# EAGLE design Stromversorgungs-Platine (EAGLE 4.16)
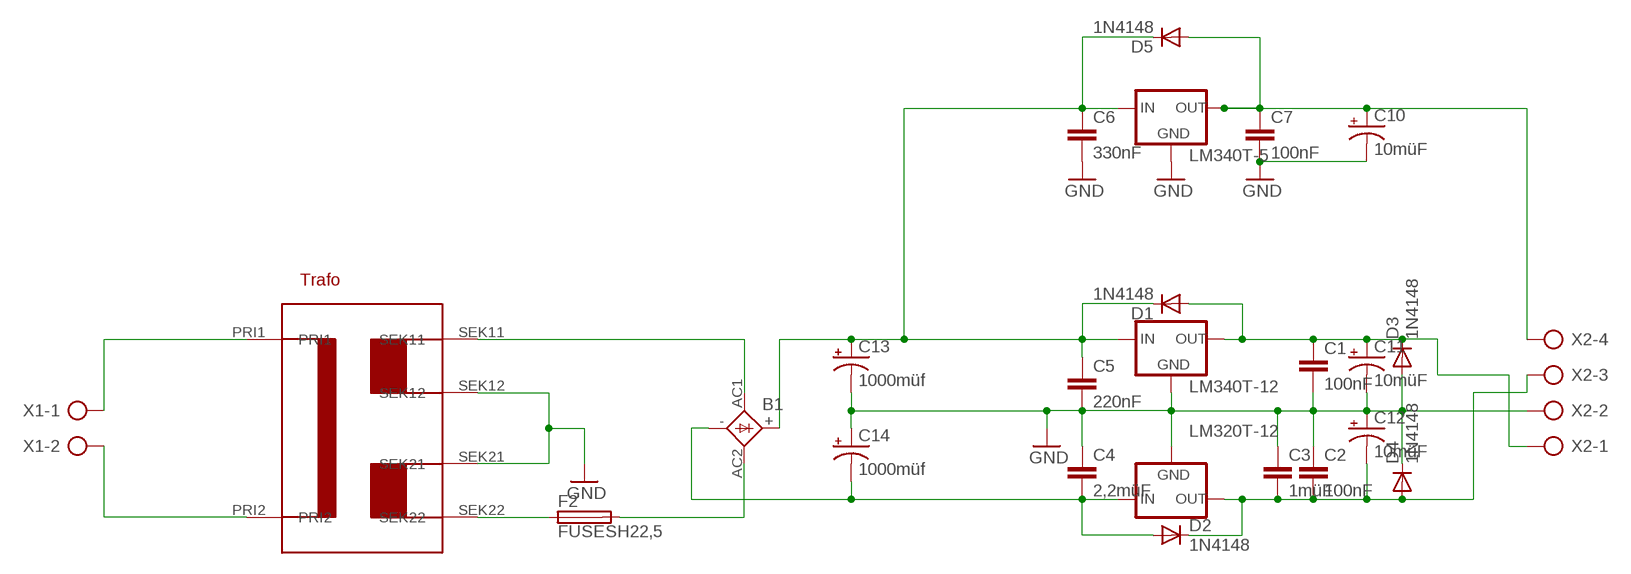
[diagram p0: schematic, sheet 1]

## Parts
B1  2KBB-R  [2KBB-R]
C1  100nF  C-EUC0805  [C0805]
C2  100nF  C-EUC0805  [C0805]
C3  1müF  C-EUC0805  [C0805]
C4  2,2müF  C-EUC0805  [C0805]
C5  220nF  C-EUC0603  [C0603]
C6  330nF  C-EUC0603  [C0603]
C7  100nF  C-EUC0805  [C0805]
C10  10müF  CPOL-USE2.5-5  [E2,5-5]
C11  10müF  CPOL-USE2.5-5  [E2,5-5]
C12  10müF  CPOL-USE2.5-5  [E2,5-5]
C13  1000müf  CPOL-USE7.5-16  [E7,5-16]
C14  1000müf  CPOL-USE7.5-16  [E7,5-16]
D1  1N4148  [DO35-10]
D2  1N4148  [DO35-10]
D3  1N4148  [DO35-10]
D4  1N4148  [DO35-10]
D5  1N4148  [DO35-10]
F2  FUSESH22,5  [SH22,5]
LM320T-12  79XXS  [79XXS]
LM340T-5  78XXS  [78XXS]
LM340T-12  78XXS  [78XXS]
U$1  TRAFO10W2X15V  [TRAFO10W2X15V]
X1  AK300/2  [AK300/2]
X2  AK300/4  [AK300/4]

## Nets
GND: C1.2 C2.1 C3.1 C4.1 C5.2 C6.2 C7.2 C10.- C11.- C12.+ C13.- C14.+ D3.A D4.C LM320T-12.GND LM340T-5.GND LM340T-12.GND U$1.SEK12 U$1.SEK21 X2.2
N$1: B1.AC1 U$1.SEK11
N$2: U$1.PRI1 X1.1
N$3: U$1.PRI2 X1.2
N$4: B1.+ C5.1 C6.1 C13.+ D1.C D5.C LM340T-5.IN LM340T-12.IN
N$5: B1.AC2 F2.2
N$6: F2.1 U$1.SEK22
N$7: C1.1 C11.+ D1.A D3.C LM340T-12.OUT X2.1
N$8: C2.2 C3.2 C12.- D2.C D4.A LM320T-12.OUT X2.3
N$9: C7.1 C10.+ D5.A LM340T-5.OUT X2.4
N$10: B1.- C4.2 C14.- D2.A LM320T-12.IN

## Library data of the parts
B1 = rectifier:2KBB-R: RECTIFIER grid 3 x 5 mm
C1-C7 = rcl:C-EU: CAPACITOR, European symbol
C10-C14 = rcl:CPOL-US: POLARIZED CAPACITOR, American symbol
D1-D5 = diode:1N4148: DIODE
F2 = fuse:FUSE: Fuse
LM320T-12 = v-reg:79XXS: VOLTAGE REGULATOR
LM340T-5 LM340T-12 = v-reg:78XXS: VOLTAGE REGULATOR
U$1 = Trafo 10W 2x15V:TRAFO10W2X15V
X1 = con-ptr500:AK300/2: CONNECTOR
X2 = con-ptr500:AK300/4: CONNECTOR

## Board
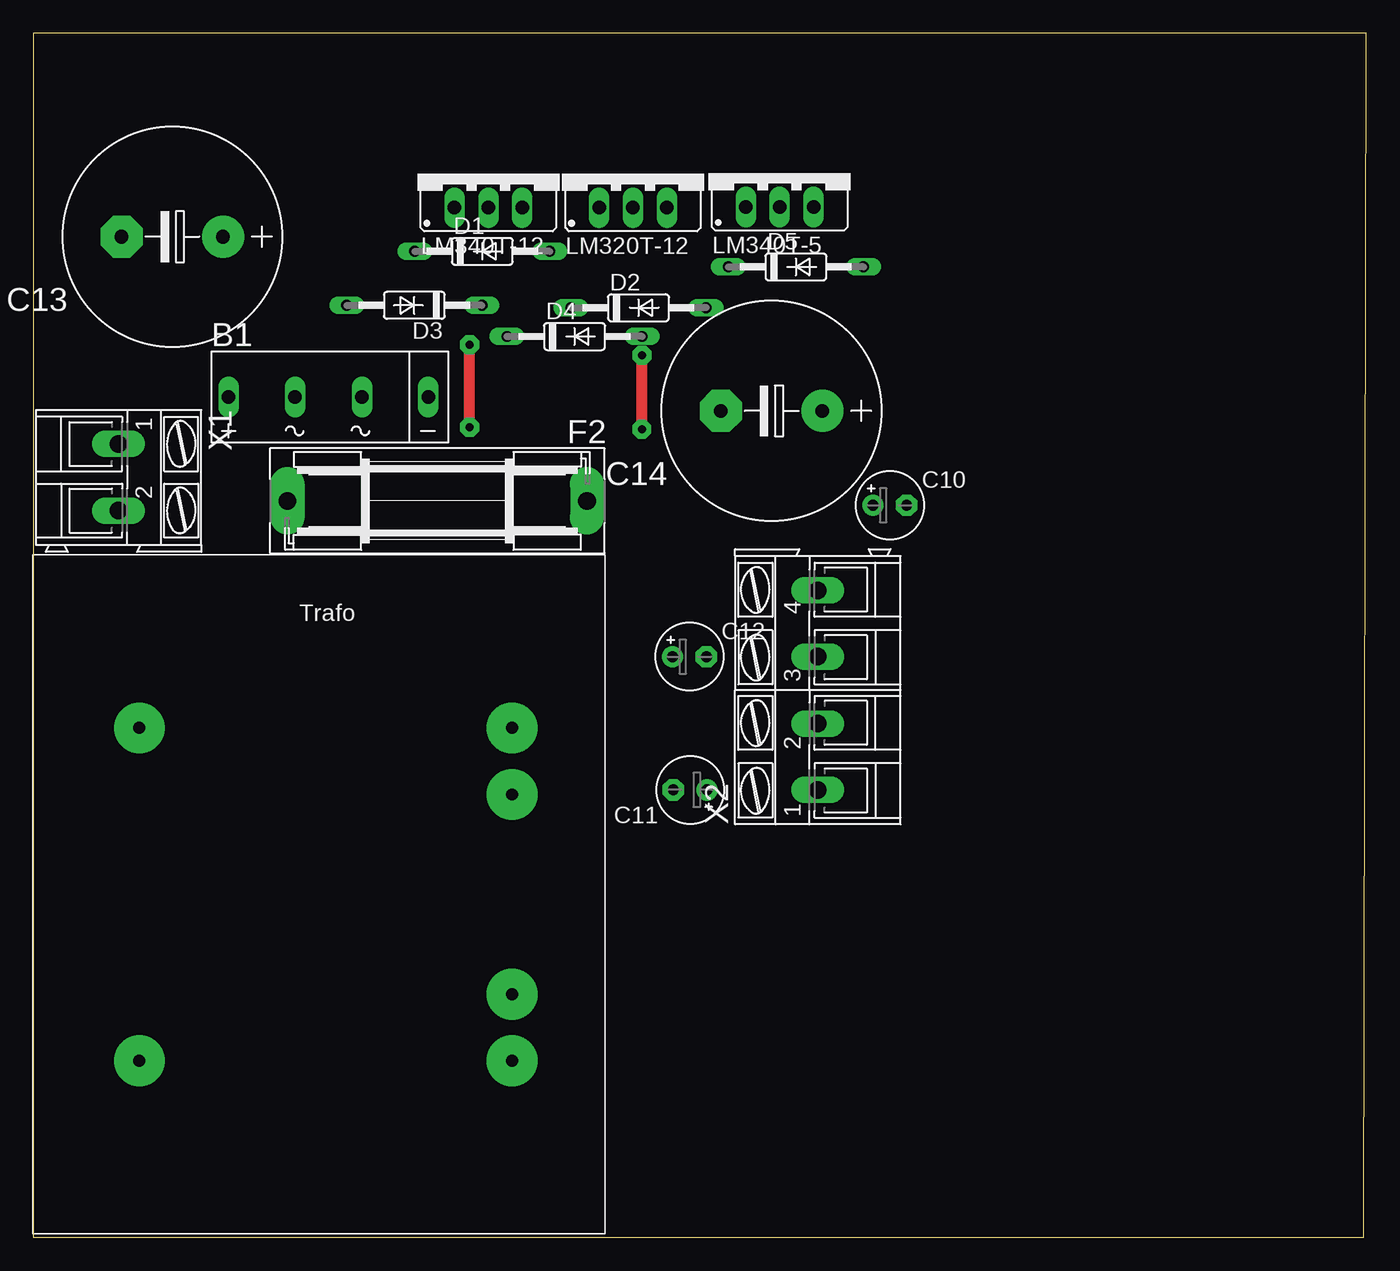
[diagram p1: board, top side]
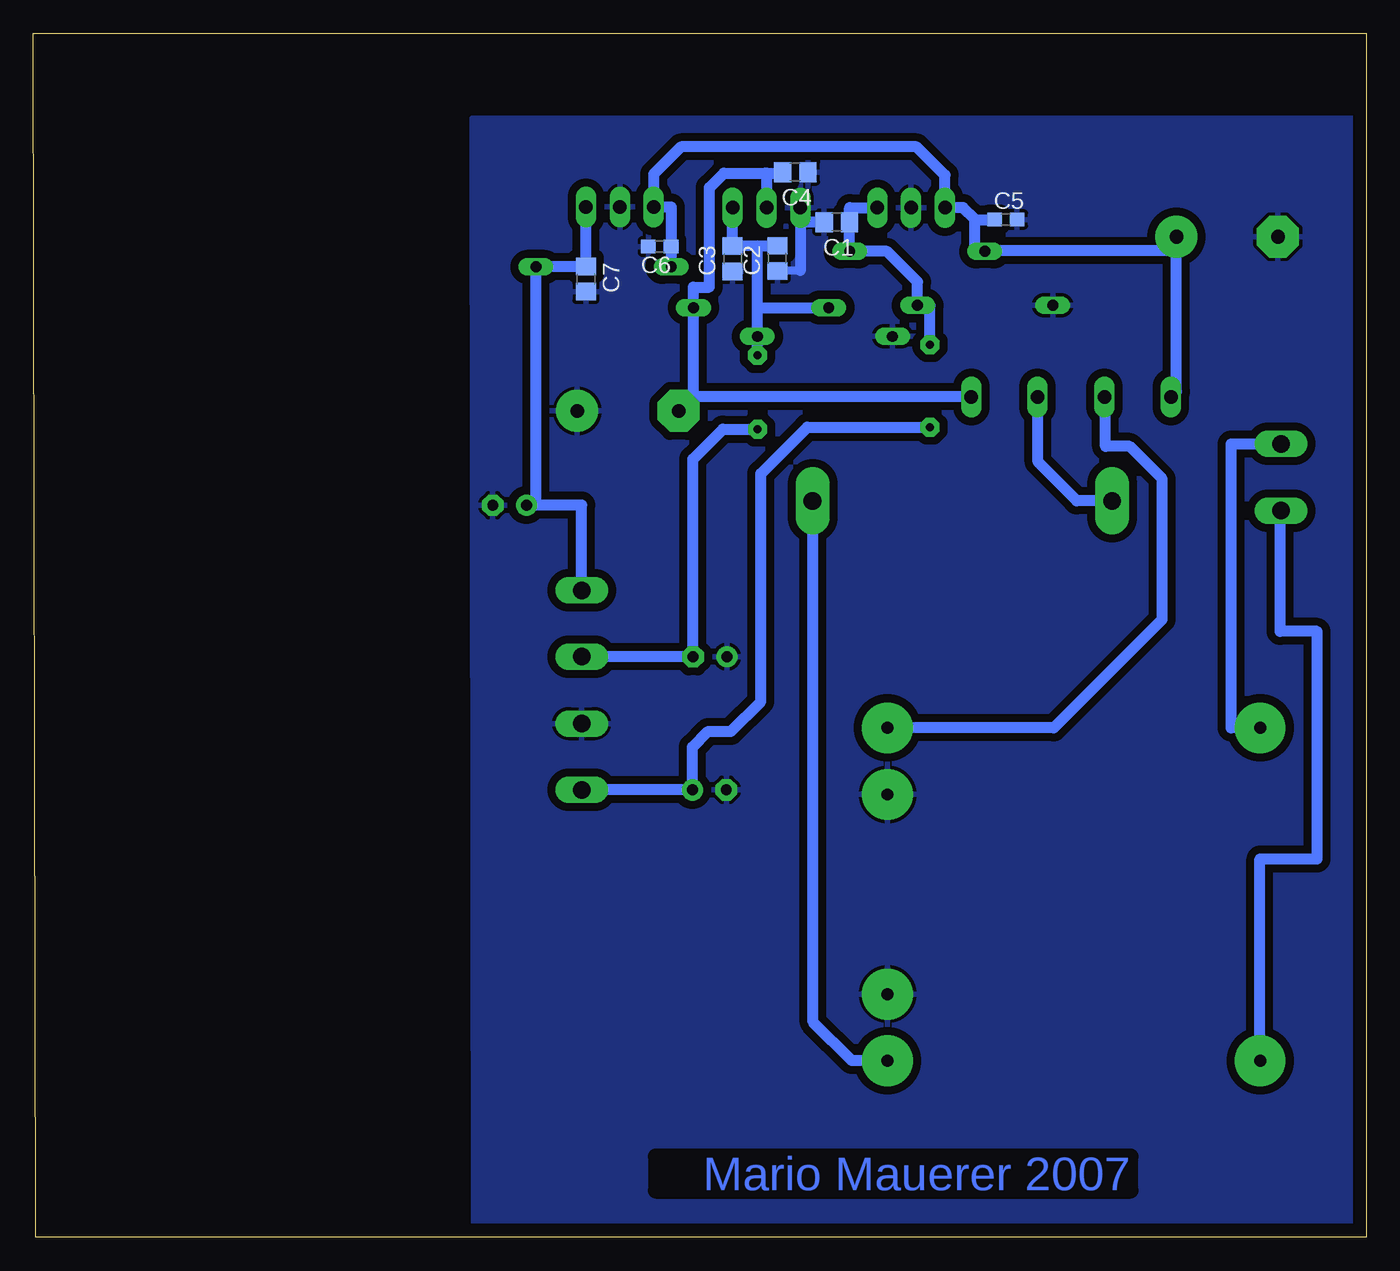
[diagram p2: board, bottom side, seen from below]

Size 100.18 x 90.46 mm. Coordinates in mm from the lower left corner, seen from the top.
Outline: 0,0 100,0 100.18,90.46 0,90.46 0,0
Copper layers (1*16): Top 0.035mm / dielectric 1.5mm / Bottom 0.035mm
Design rules "default": minimum track width 10mil, minimum drill 24mil, track to track 12mil, track to pad 12mil, pad to pad 12mil, via to via 12mil, smd to smd 8mil, copper to edge 40mil, drill to drill 8mil, minimum pad ring 10mil, minimum via ring 8mil, stop-mask expansion 4mil, vias tented up to drill 0mil, thermal gap 10mil

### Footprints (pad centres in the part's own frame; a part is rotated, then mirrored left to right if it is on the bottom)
2KBB-R = drill 1.016 long: + -7.62,0; - 7.391,0; AC1 -2.616,0; AC2 2.413,0
C0805 = smd 1.3 x 1.5: 1 -0.95,0; 2 0.95,0
C0603 = smd 1.1 x 1: 1 -0.85,0; 2 0.85,0
E2,5-5 = drill 0.813 pad 1.6 round: + -1.27,0 | drill 0.813 pad 1.6 octagon: - 1.27,0
E7,5-16 = drill 1.016 pad 3.15 round: + -3.81,0 | drill 1.016 pad 3.15 octagon: - 3.81,0
DO35-10 = drill 0.813 long: A 5.08,0; C -5.08,0
SH22,5 = drill 1.321 pad 2.54 long: 1 -11.252,0; 2 11.252,0
79XXS = drill 1.016 long: GND -2.54,-2.54; IN 0,-2.54; OUT 2.54,-2.54
78XXS = drill 1.016 long: GND 0,-2.54; IN -2.54,-2.54; OUT 2.54,-2.54
TRAFO10W2X15V = drill 0.9 pad 3.81 round: PRI1 -12,22; PRI2 -12,-3; SEK11 16,22; SEK12 16,17; SEK21 16,2; SEK22 16,-3
AK300/2 = drill 1.321 long: 1 -2.515,0; 2 2.489,0
AK300/4 = drill 1.321 long: 1 -7.493,0; 2 -2.515,0; 3 2.515,0; 4 7.493,0

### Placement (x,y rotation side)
B1  22.29,63.14 0 top
C1  39.79,76.27 180 bottom
C2  44.26,73.55 90 bottom
C3  47.61,73.53 90 bottom
C4  42.91,80.03 180 bottom
C5  27.09,76.47 0 bottom
C6  53.1,74.44 180 bottom
C7  58.64,72 270 bottom
C10  64.38,55.01 0 top
C11  49.37,33.62 180 top
C12  49.31,43.63 0 top
C13  10.45,75.18 180 top
C14  55.49,62.1 180 top
D1  33.74,74.09 0 top
D2  45.48,69.84 0 top
D3  28.64,70.02 180 top
D4  40.68,67.69 0 top
D5  57.32,72.92 0 top
F2  30.37,55.34 180 top
LM320T-12  45.07,79.9 0 top
LM340T-5  56.1,79.95 0 top
LM340T-12  34.2,79.9 0 top
U$1  19.98,16.28 0 top
X1  6.41,57.09 270 top
X2  58.97,41.12 90 top

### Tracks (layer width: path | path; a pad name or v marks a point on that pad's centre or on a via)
GND
  Bottom 0.61: 44.26,72.64 44.28,72.64 | 44.26,72.64 C2.1 | 42.53,72.64 44.26,72.64 | 42.53,76.3 42.56,76.3 42.56,76.27
  Bottom 0.813: 42.53,72.64 42.53,76.3 LM320T-12.GND | C1.2 42.56,76.27
  pour Bottom (isolate 0.61): 0.77,84.07 67.2,84.07 67.09,-0.01 0.67,-0.01
N$1
  Bottom 0.61: 19.6,63.22 19.6,63.14 B1.AC1
  Bottom 0.813: U$1.SEK11 23.49,38.28 15.33,46.43 15.33,56.99 17.77,59.43 19.6,59.43 19.6,63.14
N$2
  Bottom 0.61: X1.1 6.36,59.61 6.36,59.58
  Bottom 0.813: U$1.PRI1 10.15,38.28 10.15,59.61 6.36,59.61
N$3
  Bottom 0.813: X1.2 6.46,54.61 6.46,45.54 3.7,45.54 3.7,28.44 7.99,28.44 U$1.PRI2
N$4
  Bottom 0.61: 53.53,77.44 53.56,77.44 LM340T-5.IN
  Bottom 0.813: B1.+ 14.57,63.14 | 29.42,76.48 29.4,76.45 29.4,74.09 D1.C 28.66,74.11 14.26,74.11 C13.+ 14.26,63.55 B1.+ | 29.42,76.48 30.31,77.36 LM340T-12.IN 31.66,79.8 33.8,81.94 51.5,81.94 53.56,79.88 LM340T-5.IN 52.23,77.41 52.23,74.44 C6.1 52.26,72.92 D5.C | 29.42,76.47 29.43,76.47 | 29.42,76.48 29.42,76.47 | 29.42,76.47 C5.1 | B1.+ 14.69,63.11
N$5
  Bottom 0.61: 24.68,63.22 24.68,63.14 B1.AC2
  Bottom 0.813: F2.2 21.75,55.34 24.68,58.27 24.68,63.14
N$6
  Bottom 0.61: 41.57,55.34 F2.1
  Bottom 0.813: U$1.SEK22 38.67,13.28 41.57,16.18 41.57,55.34
N$7  (via drill 0.6 pad 1.42)
  Top 0.813: v32.78,60.88 v32.78,67.08
  Bottom 0.813: 38.82,76.27 C1.1 | LM340T-12.OUT 38.82,77.36 38.82,76.27 | 38.82,76.27 D1.A 36.02,74.09 33.72,71.79 D3.C 32.78,70.02 v32.78,67.08 | 58.99,33.62 X2.1 C11.+ 50.63,36.84 49.45,38.02 47.74,38.02 45.5,40.26 45.5,57.37 42,60.88 v32.78,60.88
N$8  (via drill 0.6 pad 1.42)
  Top 0.813: v45.73,60.73 v45.76,66.26
  Bottom 0.61: 45.76,74.49 45.76,74.52 | 45.76,74.49
  Bottom 0.813: 45.76,74.49 C2.2 | 45.76,74.49 C3.2 LM320T-12.OUT | 45.76,69.84 D4.A v45.76,66.26 | 45.76,69.84 45.76,74.49 | 45.76,69.84 D2.C | 50.61,43.63 X2.3 | C12.- 50.61,43.63 | 50.61,43.63 50.61,58.47 48.35,60.73 v45.73,60.73
N$9
  Bottom 0.406: X2.4 58.97,48.51
  Bottom 0.61: X2.4 58.99,48.61
  Bottom 0.813: C7.1 58.64,72.92 | C7.1 LM340T-5.OUT | C7.1 62.39,72.95 D5.A 62.39,55.01 62.52,55.01 | 62.52,55.01 C10.+ | X2.4 58.97,55.01 62.52,55.01
N$10
  Bottom 0.813: 45.17,79.95 48.27,79.95 49.37,78.86 49.37,71.39 50.56,71.39 D2.A 50.56,63.14 | 45.17,79.95 45.07,79.95 LM320T-12.IN | C4.2 43.86,79.95 45.17,79.95 | C14.- 51.65,62.1 51.65,63.14 50.56,63.14 | B1.- 50.56,63.14

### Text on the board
Bottom: Mario Mauerer 2007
